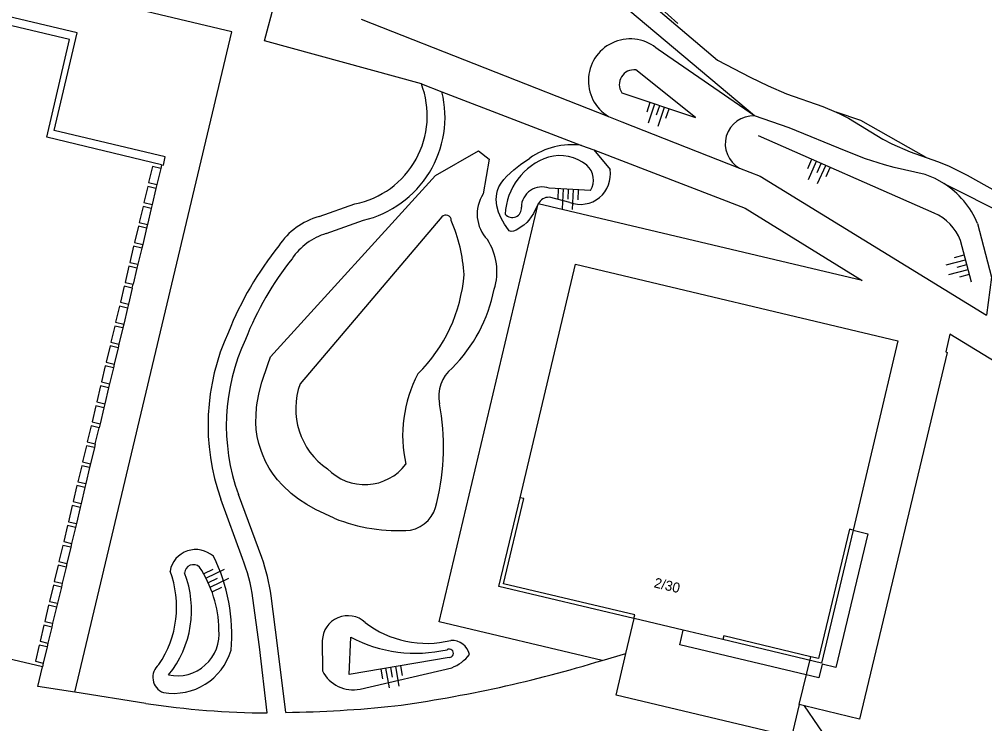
# Model space of a CAD drawing. Extents: x 131000 to 133014, y 396499 to 399001.
# Drawn here: x 131224.2 to 131320.7, y 397383.3 to 397453.8 of the extents above; entities that cross this region are included whole.
import ezdxf

# ---------------------------------------------------------------- set-up
doc = ezdxf.new("R2010")
doc.units = 0
for name, color, linetype in [('gg-anno-huisnummerreeks BGT', 7, 'Continuous'), ('gg-bbg-hoofdgebouw', 7, 'Continuous'), ('gg-bbg-luifel en loopbrug', 7, 'Continuous'), ('gg-bbg-onder overbouw', 7, 'Continuous'), ('gg-bbg-pand overbouw', 7, 'Continuous'), ('gg-knt-BGT kruinlijn', 7, 'Continuous'), ('gg-knt-bovenkant onderkant talud', 7, 'Continuous'), ('gg-knt-onverhard', 7, 'Continuous'), ('gg-knt-verharding', 7, 'Continuous'), ('gg-knt-verharding nz', 7, 'Continuous'), ('gg-kntw-bovenkant insteek waterloop', 7, 'Continuous'), ('gg-kntw-waterlijn', 7, 'Continuous'), ('gt-grn-groengrens', 7, 'Continuous'), ('gt-grn-groenlijn', 7, 'Continuous'), ('gt-symb-talud symbool', 7, 'Continuous')]:
    doc.layers.add(name, color=color, linetype=linetype)

# ---------------------------------------------------------------- blocks, each defined once
blk = doc.blocks.new('gt0-TALUD_1')
at = {"layer": 'gt-symb-talud symbool'}
for p, q in [((0, -1), (0, 0)), ((-1, -1), (-1, 0)), ((-0.5, -2), (-0.5, 0)), ((0.5, -2), (0.5, 0)), ((1, -1), (1, 0))]:
    blk.add_line(p, q, dxfattribs=at)

msp = doc.modelspace()

# ---------------------------------------------------------------- linework, layer by layer
at = {"layer": 'gg-bbg-hoofdgebouw'}
for p, q in [((131238.392, 397439.252), (131238.303, 397438.867)), ((131237.913, 397437.261), (131237.822, 397436.878)), ((131237.442, 397435.263), (131237.349, 397434.88)), ((131236.968, 397433.28), (131236.881, 397432.896)), ((131236.501, 397431.277), (131236.408, 397430.895)), ((131236.018, 397429.285), (131235.925, 397428.901)), ((131235.451, 397426.901), (131235.544, 397427.291)), ((131235.07, 397425.294), (131234.976, 397424.908)), ((131234.595, 397423.301), (131234.5, 397422.917)), ((131234.121, 397421.31), (131234.03, 397420.923)), ((131233.646, 397419.312), (131233.559, 397418.927)), ((131233.171, 397417.324), (131233.085, 397416.937)), ((131232.704, 397415.323), (131232.617, 397414.94)), ((131232.229, 397413.327), (131232.141, 397412.94)), ((131231.753, 397411.33), (131231.66, 397410.944)), ((131231.281, 397409.336), (131231.188, 397408.952)), ((131230.803, 397407.346), (131230.719, 397406.959)), ((131230.33, 397405.356), (131230.245, 397404.968)), ((131229.859, 397403.346), (131229.771, 397402.964)), ((131229.38, 397401.364), (131229.291, 397400.978)), ((131228.911, 397399.372), (131228.831, 397398.987)), ((131228.434, 397397.382), (131228.359, 397396.994)), ((131227.96, 397395.383), (131227.879, 397394.998)), ((131227.486, 397393.383), (131227.406, 397392.996)), ((131285.659, 397393.844), (131285.638, 397393.849)), ((131290.567, 397392.682), (131285.659, 397393.844)), ((131294.549, 397391.74), (131290.567, 397392.682)), ((131227.017, 397391.391), (131226.941, 397391.004)), ((131226.547, 397389.395), (131226.466, 397389.008))]:
    msp.add_line(p, q, dxfattribs=at)
for points in [[(131238.392, 397439.252), (131226.892, 397441.997), (131229.166, 397451.782), (131169.292, 397465.983), (131166.929, 397456.21), (131155.427, 397458.951)], [(131238.303, 397438.867), (131237.465, 397439.061), (131237.093, 397437.454), (131237.913, 397437.261)], [(131237.822, 397436.878), (131237.004, 397437.068), (131236.622, 397435.457), (131237.442, 397435.263)], [(131237.349, 397434.88), (131236.532, 397435.073), (131236.153, 397433.473), (131236.968, 397433.28)], [(131236.881, 397432.896), (131236.062, 397433.09), (131235.679, 397431.472), (131236.501, 397431.277)], [(131236.408, 397430.895), (131235.588, 397431.089), (131235.206, 397429.477), (131236.018, 397429.285)], [(131235.925, 397428.901), (131235.115, 397429.093), (131234.734, 397427.482), (131235.544, 397427.291)], [(131274.251, 397405.938), (131279.792, 397429.294), (131312.058, 397421.64), (131307.56, 397402.695)], [(131235.451, 397426.901), (131234.642, 397427.093), (131234.261, 397425.485), (131235.07, 397425.294)], [(131234.976, 397424.908), (131234.17, 397425.099), (131233.789, 397423.492), (131234.595, 397423.301)], [(131234.5, 397422.917), (131233.698, 397423.107), (131233.318, 397421.501), (131234.121, 397421.31)], [(131234.03, 397420.923), (131233.226, 397421.114), (131232.844, 397419.502), (131233.646, 397419.312)], [(131233.559, 397418.927), (131232.753, 397419.118), (131232.373, 397417.513), (131233.171, 397417.324)], [(131233.085, 397416.937), (131232.282, 397417.128), (131231.9, 397415.514), (131232.704, 397415.323)], [(131232.617, 397414.94), (131231.809, 397415.131), (131231.427, 397413.517), (131232.229, 397413.327)], [(131232.141, 397412.94), (131231.336, 397413.131), (131230.954, 397411.519), (131231.753, 397411.33)], [(131231.66, 397410.944), (131230.863, 397411.133), (131230.482, 397409.526), (131231.281, 397409.336)], [(131231.188, 397408.952), (131230.391, 397409.141), (131230.01, 397407.534), (131230.803, 397407.346)], [(131230.719, 397406.959), (131229.919, 397407.148), (131229.539, 397405.543), (131230.33, 397405.356)], [(131230.245, 397404.968), (131229.447, 397405.157), (131229.063, 397403.534), (131229.859, 397403.346)], [(131229.771, 397402.964), (131228.973, 397403.153), (131228.593, 397401.55), (131229.38, 397401.364)], [(131229.291, 397400.978), (131228.502, 397401.165), (131228.122, 397399.559), (131228.911, 397399.372)], [(131228.831, 397398.987), (131228.031, 397399.176), (131227.65, 397397.568), (131228.434, 397397.382)], [(131228.359, 397396.994), (131227.559, 397397.184), (131227.177, 397395.569), (131227.96, 397395.383)], [(131227.879, 397394.998), (131227.086, 397395.186), (131226.703, 397393.569), (131227.486, 397393.383)], [(131227.406, 397392.996), (131226.612, 397393.184), (131226.232, 397391.577), (131227.017, 397391.391)], [(131226.466, 397389.008), (131214.963, 397391.731), (131212.661, 397382.062)], [(131226.941, 397391.004), (131226.141, 397391.194), (131225.757, 397389.574), (131226.547, 397389.395)]]:
    msp.add_lwpolyline(points, dxfattribs=at)
at = {"layer": 'gg-bbg-luifel en loopbrug'}
msp.add_lwpolyline([(131307.56, 397402.695), (131309.054, 397402.336), (131305.848, 397388.968), (131304.458, 397389.302), (131304.125, 397387.912), (131290.222, 397391.227), (131290.567, 397392.682)], dxfattribs=at)
at = {"layer": 'gg-bbg-onder overbouw'}
for points in [[(131285.638, 397393.849), (131285.725, 397394.214), (131272.6, 397397.338), (131274.617, 397405.847), (131274.251, 397405.938)], [(131307.56, 397402.695), (131307.203, 397402.778), (131304.117, 397389.848), (131303.33, 397390.036)], [(131303.33, 397390.036), (131294.638, 397392.11), (131294.549, 397391.74)]]:
    msp.add_lwpolyline(points, dxfattribs=at)
at = {"layer": 'gg-bbg-pand overbouw'}
for points in [[(131285.638, 397393.849), (131272.141, 397397.058), (131274.251, 397405.938)], [(131307.56, 397402.695), (131304.399, 397389.398), (131294.549, 397391.74)]]:
    msp.add_lwpolyline(points, dxfattribs=at)
at = {"layer": 'gg-knt-BGT kruinlijn'}
msp.add_lwpolyline([(131316.646, 397437.38), (131315.787, 397437.879), (131314.777, 397438.258), (131311.686, 397438.954), (131310.72, 397439.22), (131308.822, 397439.841), (131306.868, 397440.587), (131301.158, 397442.925), (131297.702, 397444.134)], dxfattribs=at)
at = {"layer": 'gg-knt-bovenkant onderkant talud'}
for p, q in [((131297.702, 397444.134), (131288.066, 397450.766)), ((131315.676, 397434.405), (131298.112, 397442.14)), ((131281.644, 397440.735), (131283.25, 397438.769)), ((131281.291, 397436.675), (131277.172, 397436.9)), ((131279.226, 397435.481), (131277.183, 397435.99)), ((131319.408, 397427.513), (131318.315, 397431.673)), ((131254.465, 397391.642), (131254.477, 397388.606)), ((131258.247, 397386.794), (131267.413, 397388.928))]:
    msp.add_line(p, q, dxfattribs=at)
for points in [[(131284.424, 397446.454), (131291.815, 397443.956), (131285.834, 397448.723)], [(131276.062, 397435.335), (131275.586, 397434.357), (131275.139, 397433.711), (131274.936, 397433.476), (131274.611, 397433.194), (131273.858, 397432.702), (131273.607, 397432.596), (131273.374, 397432.569), (131273.268, 397432.594), (131273.17, 397432.65), (131273.083, 397432.74), (131272.69, 397433.312), (131272.358, 397433.906), (131272.102, 397434.517), (131271.934, 397435.136), (131271.869, 397435.756), (131271.879, 397436.064), (131271.92, 397436.37), (131271.993, 397436.673), (131272.142, 397437.046), (131272.358, 397437.414), (131272.627, 397437.773), (131272.935, 397438.118), (131273.614, 397438.751), (131274.287, 397439.277), (131275.219, 397439.899)], [(131320.016, 397433.372), (131321.428, 397428.005), (131320.906, 397424.194)], [(131267.147, 397389.966), (131257.145, 397388.243), (131257.308, 397391.988)]]:
    msp.add_lwpolyline(points, dxfattribs=at)
for centre, radius, start, end in [((131285.271, 397447.648), 4.188, 48.11929, 238.7318), ((131285.638, 397447.272), 1.464, 82.29417, 213.99061), ((131297.563, 397441.35), 2.787, 87.1513, 240.92601), ((131279.423, 397434.02), 7.228, 82.33059, 125.5697), ((131279.113, 397433.974), 6.365, 108.61723, 177.10872), ((131278.215, 397435.859), 4.299, 50.97631, 105.29299), ((131280.298, 397438.275), 2.993, 249.00428, 9.50006), ((131279.656, 397437.725), 1.943, 327.28875, 49.34629), ((131311.923, 397429.988), 8.772, 22.69189, 57.42359), ((131276.444, 397434.965), 2.067, 69.37466, 179.26395), ((131277.142, 397434.774), 1.217, 88.05717, 152.5383), ((131273.465, 397434.88), 0.919, 219.54068, 6.99294), ((131313.759, 397429.913), 4.884, 21.12418, 66.89184), ((131241.814, 397398.126), 2.625, 47.97488, 169.5987), ((131227.769, 397392.216), 17.649, 355.01581, 26.44513), ((131241.571, 397398.361), 0.878, 46.93682, 177.08007), ((131232.519, 397392.558), 11.606, 1.03081, 33.73164), ((131229.676, 397395.002), 10.211, 325.67574, 20.63533), ((131231.079, 397394.702), 10.304, 320.94992, 21.07078), ((131257.027, 397391.575), 2.563, 47.51109, 178.50541), ((131264.909, 397401.423), 10.058, 232.29832, 283.93784), ((131239.943, 397392.324), 4.203, 258.15888, 6.05617), ((131263.805, 397404.281), 13.904, 242.14374, 283.0519), ((131267.432, 397389.876), 1.788, 12.0054, 93.2207), ((131239.539, 397392.435), 6.07, 260.75951, 343.22849), ((131267.164, 397390.382), 0.416, 267.64314, 121.75606), ((131265.951, 397392.731), 4.074, 291.03509, 322.45541), ((131239.162, 397387.978), 1.647, 129.73861, 248.71469), ((131257.558, 397390.189), 3.464, 207.18644, 281.47227)]:
    msp.add_arc(centre, radius, start, end, dxfattribs=at)
at = {"layer": 'gg-knt-onverhard'}
msp.add_line((131316.646, 397437.38), (131323.079, 397434.132), dxfattribs=at)
for points in [[(131254.286, 397485.874), (131262.98, 397477.66), (131283.472, 397458.683), (131293.993, 397449.721), (131297.256, 397447.999), (131299.058, 397447.13), (131300.898, 397446.343), (131304.549, 397445.055), (131305.867, 397444.508)], [(131297.702, 397444.134), (131277.975, 397460.752), (131264.759, 397472.423), (131254.95, 397481.732)], [(131305.867, 397444.508), (131306.241, 397444.353), (131307.123, 397443.891), (131310.545, 397441.804), (131311.436, 397441.327), (131313.273, 397440.548), (131314.892, 397439.971)], [(131314.892, 397439.971), (131316.105, 397439.538), (131317.196, 397439.099), (131318.987, 397438.219), (131322.909, 397436.003), (131324.695, 397435.095), (131326.524, 397434.287), (131329.002, 397433.403), (131336.978, 397431.059)]]:
    msp.add_lwpolyline(points, dxfattribs=at)
at = {"layer": 'gg-knt-verharding'}
for p, q in [((131258.365, 397453.793), (131283.097, 397444.069)), ((131266.437, 397446.525), (131280.388, 397441.183)), ((131283.097, 397444.069), (131284.424, 397443.547)), ((131284.424, 397443.547), (131296.209, 397438.914)), ((131280.388, 397441.183), (131281.644, 397440.735)), ((131238.303, 397438.867), (131237.913, 397437.261)), ((131237.822, 397436.878), (131237.442, 397435.263)), ((131237.349, 397434.88), (131236.968, 397433.28)), ((131254.142, 397434.054), (131257.731, 397435.327)), ((131254.852, 397432.363), (131258.573, 397433.691)), ((131236.881, 397432.896), (131236.501, 397431.277)), ((131236.408, 397430.895), (131236.018, 397429.285)), ((131235.925, 397428.901), (131235.544, 397427.291)), ((131235.451, 397426.901), (131235.07, 397425.294)), ((131234.976, 397424.908), (131234.595, 397423.301)), ((131234.5, 397422.917), (131234.121, 397421.31)), ((131234.03, 397420.923), (131233.646, 397419.312)), ((131233.559, 397418.927), (131233.171, 397417.324)), ((131233.085, 397416.937), (131232.704, 397415.323)), ((131232.617, 397414.94), (131232.229, 397413.327)), ((131231.753, 397411.33), (131232.141, 397412.94)), ((131231.66, 397410.944), (131231.281, 397409.336)), ((131231.188, 397408.952), (131230.803, 397407.346)), ((131230.719, 397406.959), (131230.33, 397405.356)), ((131246.471, 397399.865), (131244.305, 397405.807)), ((131248.423, 397399.945), (131246.075, 397406.252)), ((131230.245, 397404.968), (131229.859, 397403.346)), ((131229.771, 397402.964), (131229.38, 397401.364)), ((131229.291, 397400.978), (131228.911, 397399.372)), ((131228.831, 397398.987), (131228.434, 397397.382)), ((131228.359, 397396.994), (131227.96, 397395.383)), ((131227.879, 397394.998), (131227.486, 397393.383)), ((131227.406, 397392.996), (131227.017, 397391.391)), ((131226.941, 397391.004), (131226.547, 397389.395)), ((131236.826, 397385.359), (131229.695, 397386.483)), ((131305.466, 397381.101), (131302.712, 397385.117))]:
    msp.add_line(p, q, dxfattribs=at)
for points in [[(131229.695, 397386.483), (131245.409, 397452.548), (131155.132, 397473.992), (131143.016, 397423.196), (131122.779, 397428.138)], [(131238.392, 397439.252), (131238.564, 397439.21), (131238.759, 397440.027), (131227.654, 397442.659), (131229.944, 397452.431), (131168.522, 397467.015), (131166.238, 397457.273), (131155.488, 397459.82), (131155.289, 397458.984), (131155.427, 397458.951)], [(131264.376, 397447.344), (131248.696, 397451.646), (131249.724, 397455.52), (131249.463, 397456.423)], [(131281.644, 397440.735), (131296.785, 397434.916), (131308.48, 397427.679), (131276.062, 397435.335)], [(131296.209, 397438.914), (131298.287, 397438.097), (131320.906, 397424.194)], [(131282.461, 397389.67), (131266.152, 397393.517), (131276.062, 397435.335)], [(131340.856, 397408.652), (131329.805, 397414.618), (131317.26, 397422.307), (131316.854, 397420.517), (131316.974, 397420.479), (131308.211, 397383.783), (131302.712, 397385.117)], [(131248.964, 397384.406), (131248.197, 397391.033), (131247.505, 397395.895)], [(131250.81, 397384.459), (131249.991, 397391.169), (131249.344, 397396.115)]]:
    msp.add_lwpolyline(points, dxfattribs=at)
for centre, radius, start, end in [((131255.977, 397444.142), 8.988, 281.25058, 20.86716), ((131256.149, 397444.003), 10.593, 283.23059, 13.77386), ((131255.923, 397427.369), 6.918, 104.91799, 147.10969), ((131256.651, 397426.348), 6.278, 106.6523, 146.15302), ((131276.767, 397409.765), 34.157, 141.28951, 158.12337), ((131276.27, 397410.123), 31.712, 141.54349, 158.43422), ((131265.2, 397413.209), 22.167, 155.24305, 199.50665), ((131265.154, 397413.168), 20.293, 154.89093, 199.92436), ((131232.559, 397394.122), 15.051, 6.7656, 22.4315), ((131229.2, 397393.297), 20.34, 7.96439, 19.07799), ((131244.149, 397514.517), 130.593, 277.72782, 287.05952), ((131249.379, 397467.468), 83.063, 261.30773, 269.71367), ((131249.087, 397504.882), 120.435, 270.81962, 276.01621)]:
    msp.add_arc(centre, radius, start, end, dxfattribs=at)
at = {"layer": 'gg-knt-verharding nz'}
for p, q in [((131264.376, 397447.344), (131266.437, 397446.525)), ((131284.83, 397390.341), (131285.659, 397393.844)), ((131282.461, 397389.67), (131284.83, 397390.341)), ((131302.184, 397385.236), (131303.33, 397390.036)), ((131302.712, 397385.117), (131302.184, 397385.236))]:
    msp.add_line(p, q, dxfattribs=at)
for points in [[(131302.184, 397385.236), (131301.402, 397382.023), (131283.849, 397386.199), (131284.83, 397390.341)], [(131229.695, 397386.483), (131226.011, 397387.063), (131226.466, 397389.008)]]:
    msp.add_lwpolyline(points, dxfattribs=at)
at = {"layer": 'gg-kntw-bovenkant insteek waterloop'}
msp.add_lwpolyline([(131255.654, 397403.879), (131253.801, 397404.775), (131252.922, 397405.264), (131252.069, 397405.806), (131251.338, 397406.37), (131250.484, 397407.184), (131249.99, 397407.729), (131249.549, 397408.294), (131249.153, 397408.897), (131248.797, 397409.554), (131248.474, 397410.283), (131248.333, 397410.653), (131248.109, 397411.368), (131247.954, 397412.064), (131247.861, 397412.757), (131247.823, 397413.463), (131247.833, 397414.197), (131247.882, 397414.975), (131247.938, 397415.441), (131248.139, 397416.451), (131248.417, 397417.489), (131249.003, 397419.268), (131249.288, 397420.029), (131265.79, 397438.16), (131270.079, 397440.63), (131271.17, 397439.798), (131270.56, 397436.322)], dxfattribs=at)
for centre, radius, start, end in [((131273.647, 397434.301), 3.69, 146.79191, 223.64219), ((131266.129, 397428.556), 5.809, 342.25889, 33.41652), ((131256.692, 397429.721), 15.254, 314.84965, 348.90502), ((131269.72, 397416.103), 3.608, 128.9909, 192.14417), ((131243.872, 397411.03), 22.734, 345.83732, 10.93789), ((131262.578, 397405.978), 3.376, 282.35232, 351.31556), ((131262.135, 397420.227), 17.585, 248.37571, 273.79988)]:
    msp.add_arc(centre, radius, start, end, dxfattribs=at)
at = {"layer": 'gg-kntw-waterlijn'}
msp.add_line((131266.428, 397434.041), (131252.246, 397417.336), dxfattribs=at)
for centre, radius, start, end in [((131266.827, 397433.676), 0.541, 358.0769, 137.5439), ((131252.507, 397427.276), 16.172, 3.4594, 23.24247), ((131252.972, 397429.514), 15.729, 314.61025, 355.39702), ((131275.731, 397412.17), 13.228, 152.3092, 192.62859), ((131259.061, 397414.834), 7.26, 159.83964, 235.79727), ((131258.709, 397412.432), 5.184, 224.00817, 322.53031)]:
    msp.add_arc(centre, radius, start, end, dxfattribs=at)
at = {"layer": 'gt-grn-groengrens'}
msp.add_lwpolyline([(131314.892, 397439.971), (131308.331, 397443.686), (131305.867, 397444.508)], dxfattribs=at)
at = {"layer": 'gt-grn-groenlijn'}
msp.add_line((131290.044, 397453.36), (131272.398, 397469.399), dxfattribs=at)

# ---------------------------------------------------------------- block references
at = {"layer": 'gt-symb-talud symbool'}
for p, xscale, yscale, rotation in [((131288.222, 397445.171), 0.9996044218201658, 0.9996044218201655, -18.6705834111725), ((131304.368, 397439.385), 0.999816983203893, 0.9998169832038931, -23.770475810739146), ((131279.111, 397436.794), 1.0005128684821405, 1.0005128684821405, -3.151240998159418), ((131318.948, 397429.263), 0.9998024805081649, 0.9998024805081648, -75.28268885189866), ((131243.053, 397397.43), 0.9996824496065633, 0.9996824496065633, 115.5397328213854), ((131261.328, 397388.964), 0.9995624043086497, 0.9995624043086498, 9.792146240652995)]:
    msp.add_blockref('gt0-TALUD_1', p, dxfattribs=dict(at, xscale=xscale, yscale=yscale, rotation=rotation))

# ---------------------------------------------------------------- texts
at = {"layer": 'gg-anno-huisnummerreeks BGT'}
msp.add_text('2/30', height=1, rotation=346.7, dxfattribs=at).set_placement((131287.586, 397396.984))

doc.saveas('drawing.dxf')
